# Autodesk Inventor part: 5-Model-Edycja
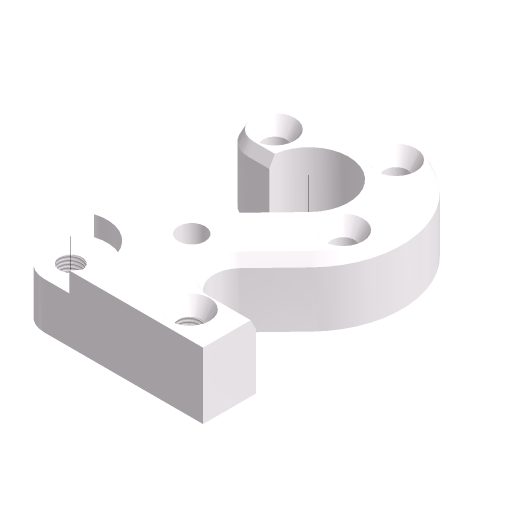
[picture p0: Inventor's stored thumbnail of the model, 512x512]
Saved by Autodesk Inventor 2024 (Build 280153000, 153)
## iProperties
Company: ATC
Shininess: 21.0
Length Units: 11269
Angle Units: 11279
Time Units: 11290
Mass Units: 11283
Compacted: True
Created: 2023-03
Part Number: 5-Model-Edycja
Document SubType Name: Modeling
Designer: Andrzej Jaskulski
Material: Kurs-AJ
Density: 1 g/cm^3
Appearance: Kurs-AJ
Checked By: A.J.
Engr Approved By: Andrzej Jaskulski
Mfg Approved By: Andrzej Jaskulski
Authority: A.J.
Density: 0.0
Volumn: 0.0
Area: 0.0
PropertySet Name: Model Information
Control State: 0
Master: False
Checked Out: False
Title: A.J.: Kurs R2024-MEP
Author: Andrzej Jaskulski
Revision Number: 1/24
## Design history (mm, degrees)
sketch "Zarys dwójki"
  geometry: L1 (140, 0.063)-(0, 0.063) reference; L2 (0, 0.063)-(0, 34.389) reference; L3 (0, 150.063)-(40, 150.063); L4 (140, 0.063)-(140, 40.063); L5 (140, 40.063)-(61.086, 40.063); L6 (61.086, 40.063)-(120.354, 101.437); L7 (91.58, 129.223)-(0, 34.389); A1 r 30 centre (70, 150.063) between (91.58, 129.223) and (40, 150.063); A2 r 70 centre (70, 150.063) between (120.354, 101.437) and (0, 150.063)
  constraints: 14 end point, 4 perpendicular, 4 point on circle, 2 centre point, 2 parallel, 2 tangent, 1 coincident
  dimensions: "d0" = 140 distance of L1.start L1.end; "d1" = 150 vertical distance of A1.centre L1.end; "d2" = 70 horizontal distance of L1.end A1.centre; "d3" = 46 deg angle of L6 L5; "d4" = 150 distance of L3.start L1.end (= d1); "d5" = 30 radius of A1; "d6" = 70 radius of A2
extrude "Dwójka" new body sketch "Zarys dwójki" distance "d7" = 50; taper "d8" = 0 deg
node "Oś walca"
sketch "Szkic Ow"
  geometry: A1 r 20 centre (20, 20.063) between (0, 20.063) and (20, 0.063) reference
hole "Otwór W" sketch "Szkic Ow" at (20, 20.063) diameter "d15" = 17; stored, may be unused: countersink angle "d19" = 60 deg, drill point angle "d21" = 118 deg; dims "d16" = 42, "d17" = 55, "d18" = 15, "d20" = 45
node "Oś Otworu W"
sketch "Szkic OSt"
  geometry: L1 (140, 0.063)-(38.875, 0.063) reference; L2 (140, 36.063)-(140, 0.063) reference; 1 further point
  dimensions: "d24" = 20 distance from line of point (110, 20.063) L1; "d25" = 30 distance from line of L2 point (110, 20.063)
hole "Otwór St" sketch "Szkic OSt" at (110, 20.063) diameter "d26" = 17.4; stored, may be unused: countersink angle "d30" = 60 deg, drill point angle "d32" = 118 deg; dims "d27" = 12, "d28" = 30, "d29" = 15, "d31" = 45
sketch "Szkic OZw"
  geometry: L1 (11.385, 46.179)-(91.58, 129.223) reference; L2 (61.221, 70.32)-(25.575, 33.408); C1 r 15 at (110, 20.063) reference; A1 r 27.5 centre (20, 20.063) between (38.875, 0.063) and (11.385, 46.179) reference
  constraints: 2 end point, 1 parallel
  dimensions: "d33" = 70 distance from line of L2 C1.centre; "d34" = 65 distance of L2.start A1.centre
hole "Otwór Zw" sketch "Szkic OZw" at (61.221, 70.32) diameter "d35" = 20; stored, may be unused: countersink angle "d39" = 60 deg, drill point angle "d41" = 118 deg; dims "d36" = 12, "d37" = 30, "d38" = 15, "d40" = 45
feature "Gwint OSt" dims "d42" = 10, "d43" = 0
sketch "Oś otworu"
  geometry: A1 r 16 centre (85.597, -3.545) between (70.932, 2.855) and (85.597, -19.545) reference; 1 further point
  constraints: 1 coincident
hole "Oryginał" sketch "Oś otworu" at (85.597, -3.545) diameter "d61" = 17.4 (= d26); stored, may be unused: drill point angle "d56" = 118 deg, countersink angle "d57" = 60 deg (= d30); dims "d53" = 12 (= d27), "d58" = 15, "d59" = 30 (= d28), "d60" = 45
pattern_circular "Szyk kołowy 1" dims angle "d71" = 180 deg
node "Bryła1"
node "Korpusy bryłowe"
node "Korpusy powierzchniowe"
fillet "Zaokrąglenie" dims "d12" = 20
chamfer "Faza" distance "d13" = 4; stored, may be unused: second distance "d14" = 8, angle "d68" = 45 deg
other parameters: "d9" = 90 deg
